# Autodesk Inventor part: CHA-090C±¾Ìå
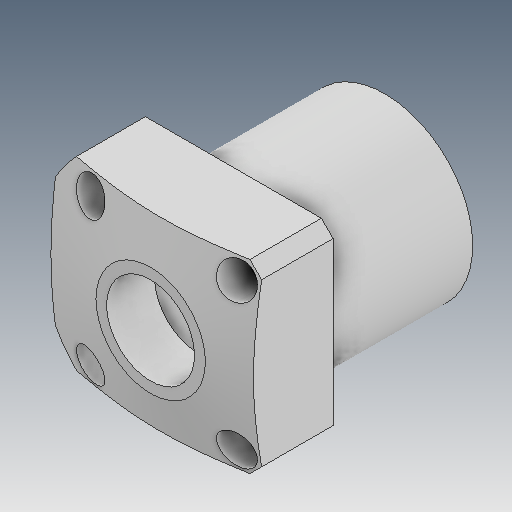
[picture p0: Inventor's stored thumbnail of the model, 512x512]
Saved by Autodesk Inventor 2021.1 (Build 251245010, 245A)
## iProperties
Created: 2019-05
Part Number: CHA-090C±¾Ìå
Material: Ogólny
Document SubType Name: Modeling
Designer: user
Density: 1 g/cm^3
Appearance: Domyślna
Author: user
Revision Number: ÈÎºÎ
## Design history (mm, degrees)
feature "ÊäÈë1"
node "Bryła1"
